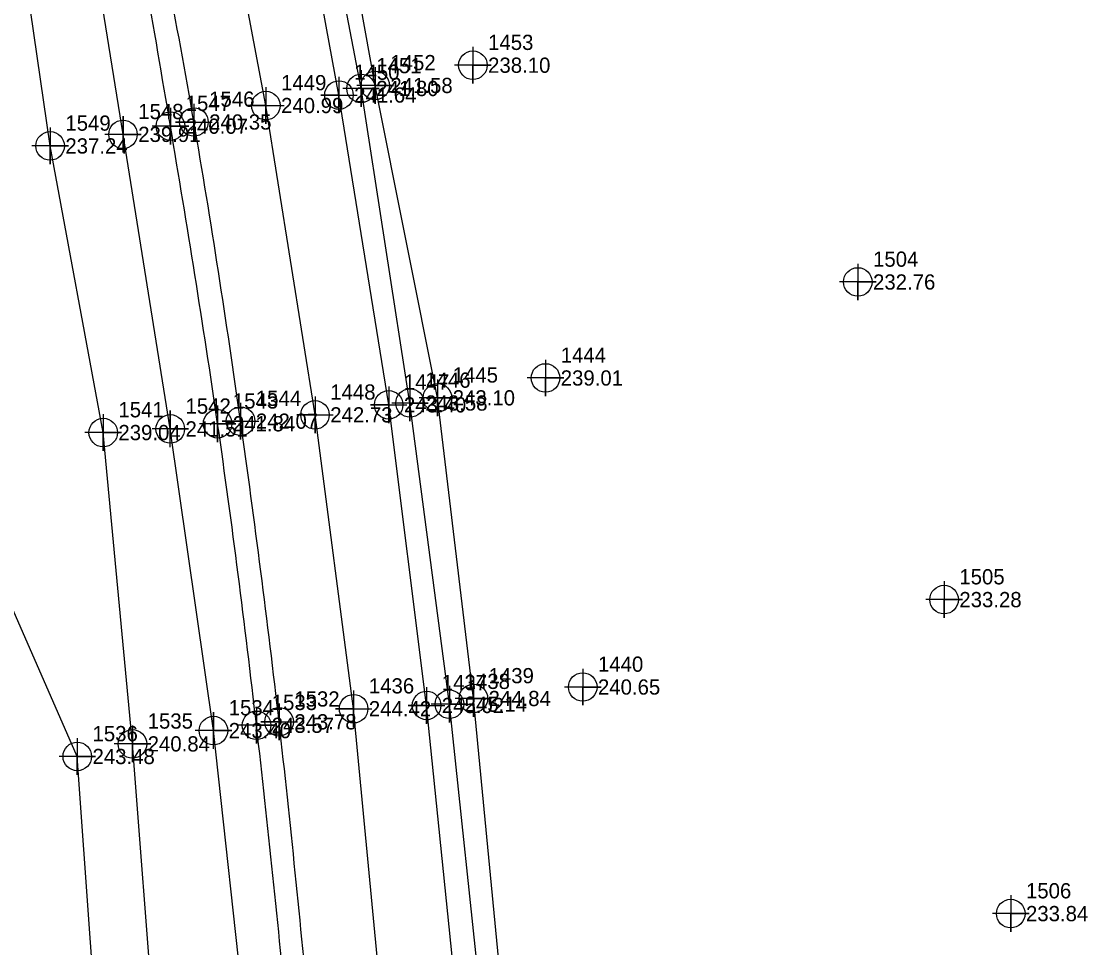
# Model space of a CAD drawing. Extents: x 2130962 to 2131465, y 643052 to 644206.
# Drawn here: x 2131170.6 to 2131345.6, y 643479.2 to 643631.2 of the extents above; entities that cross this region are included whole.
import ezdxf

# ---------------------------------------------------------------- set-up
doc = ezdxf.new("R2010")
doc.units = 0
for name, color, linetype in [('Exist DTM Breakline', 7, 'Continuous'), ('Exist DTM Breakline Cogo Elevation', 7, 'Continuous'), ('Exist DTM Breakline Cogo Number', 7, 'Continuous'), ('Exist DTM Breakline Cogo Point CELL', 7, 'Continuous'), ('Exist DTM Drainline', 7, 'Continuous'), ('Exist DTM Drainline Cogo Elevation', 7, 'Continuous'), ('Exist DTM Drainline Cogo Number', 7, 'Continuous'), ('Exist DTM Drainline Cogo Point CELL', 7, 'Continuous'), ('Exist DTM Regular Point CELL', 7, 'Continuous'), ('Exist DTM Regular Point Cogo Elevation', 7, 'Continuous'), ('Exist DTM Regular Point Cogo Number', 7, 'Continuous'), ('Exist Roads EOP', 7, 'Continuous'), ('Exist Roads EOP Cogo Elevation', 7, 'Continuous'), ('Exist Roads EOP Cogo Number', 7, 'Continuous'), ('Exist Roads EOP Cogo Point CELL', 7, 'Continuous'), ('Exist Roads EOT', 7, 'Continuous'), ('Exist Roads EOT Cogo Elevation', 7, 'Continuous'), ('Exist Roads EOT Cogo Number', 7, 'Continuous'), ('Exist Roads EOT Cogo Point CELL', 7, 'Continuous'), ('Exist Roads Soil', 7, 'Continuous'), ('Exist Roads Soil Cogo Elevation', 7, 'Continuous'), ('Exist Roads Soil Cogo Number', 7, 'Continuous'), ('Exist Roads Soil Cogo Point CELL', 7, 'Continuous')]:
    doc.layers.add(name, color=color, linetype=linetype)

msp = doc.modelspace()

# ---------------------------------------------------------------- linework, layer by layer
at = {"layer": 'Exist DTM Breakline'}
for points in [[(2131266.3306, 643269.372), (2131264.0776, 643319.4437), (2131258.8396, 643369.5498), (2131255.3671, 643419.5794), (2131249.6414, 643469.556), (2131244.7652, 643520.0623), (2131238.8778, 643569.4077), (2131228.6495, 643620.6699), (2131219.85, 643669.4823), (2131206.9682, 643717.8453), (2131195.8132, 643768.1497), (2131183.2404, 643816.8151), (2131169.0496, 643865.1461), (2131151.2314, 643913.4424), (2131130.7295, 643958.9736), (2131122.7411, 643983.0115)], [(2131000.7408, 643235.0731), (2131050.2503, 643235.0771), (2131099.3971, 643233.3967), (2131102.4734, 643233.467), (2131117.9784, 643240.6457), (2131141.4902, 643260.2289), (2131148.9668, 643267.309), (2131161.3925, 643274.3195), (2131169.1458, 643283.2692), (2131172.0772, 643292.493), (2131174.434, 643316.7319), (2131174.0607, 643347.0813), (2131174.2633, 643367.3367), (2131180.4607, 643413.966), (2131183.0424, 643464.7744), (2131179.7562, 643510.5479), (2131157.5016, 643561.2065), (2131139.0887, 643604.6918), (2131124.996, 643650.6897)]]:
    msp.add_lwpolyline(points, dxfattribs=at)
at = {"layer": 'Exist DTM Breakline Cogo Point CELL'}
for points in [[(2131228.6495, 643623.6699), (2131228.6495, 643617.6699), (2131228.6495, 643620.6699), (2131231.6495, 643620.6699), (2131225.6495, 643620.6699)], [(2131238.8778, 643572.4077), (2131238.8778, 643566.4077), (2131238.8778, 643569.4077), (2131241.8778, 643569.4077), (2131235.8778, 643569.4077)], [(2131244.7652, 643523.0623), (2131244.7652, 643517.0623), (2131244.7652, 643520.0623), (2131247.7652, 643520.0623), (2131241.7652, 643520.0623)], [(2131179.7562, 643513.5479), (2131179.7562, 643507.5479), (2131179.7562, 643510.5479), (2131182.7562, 643510.5479), (2131176.7562, 643510.5479)]]:
    msp.add_lwpolyline(points, dxfattribs=at)
for centre in [(2131228.6495, 643620.6699), (2131238.8778, 643569.4077), (2131244.7652, 643520.0623), (2131179.7562, 643510.5479)]:
    msp.add_circle(centre, 2.344, dxfattribs=at)
at = {"layer": 'Exist DTM Drainline'}
msp.add_lwpolyline([(2131000.2029, 643226.7228), (2131050.9884, 643228.9032), (2131099.0297, 643228.5605), (2131120.2968, 643239.3591), (2131144.9156, 643253.3469), (2131146.4739, 643252.3674), (2131154.3188, 643256.8046), (2131168.9618, 643265.5132), (2131176.6257, 643272.964), (2131179.8144, 643285.303), (2131183.3842, 643315.022), (2131190.1471, 643365.8731), (2131190.1489, 643413.686), (2131192.3886, 643466.4632), (2131188.8083, 643512.615), (2131184.0059, 643563.7066), (2131175.3, 643610.7482), (2131168.3784, 643658.7431), (2131156.7476, 643707.4708), (2131144.9036, 643754.0458), (2131132.9438, 643802.544), (2131118.0831, 643847.9475), (2131104.0084, 643896.8663), (2131096.3866, 643919.4077)], dxfattribs=at)
at = {"layer": 'Exist DTM Drainline Cogo Point CELL'}
for points in [[(2131175.3, 643613.7482), (2131175.3, 643607.7482), (2131175.3, 643610.7482), (2131178.3, 643610.7482), (2131172.3, 643610.7482)], [(2131184.0059, 643566.7066), (2131184.0059, 643560.7066), (2131184.0059, 643563.7066), (2131187.0059, 643563.7066), (2131181.0059, 643563.7066)], [(2131188.8083, 643515.615), (2131188.8083, 643509.615), (2131188.8083, 643512.615), (2131191.8083, 643512.615), (2131185.8083, 643512.615)]]:
    msp.add_lwpolyline(points, dxfattribs=at)
for centre in [(2131175.3, 643610.7482), (2131184.0059, 643563.7066), (2131188.8083, 643512.615)]:
    msp.add_circle(centre, 2.344, dxfattribs=at)
at = {"layer": 'Exist DTM Regular Point CELL'}
for points in [[(2131244.6876, 643626.9964), (2131244.6876, 643620.9964), (2131244.6876, 643623.9964), (2131247.6876, 643623.9964), (2131241.6876, 643623.9964)], [(2131307.874, 643591.4198), (2131307.874, 643585.4198), (2131307.874, 643588.4198), (2131310.874, 643588.4198), (2131304.874, 643588.4198)], [(2131256.6081, 643575.6655), (2131256.6081, 643569.6655), (2131256.6081, 643572.6655), (2131259.6081, 643572.6655), (2131253.6081, 643572.6655)], [(2131322.0371, 643539.2918), (2131322.0371, 643533.2918), (2131322.0371, 643536.2918), (2131325.0371, 643536.2918), (2131319.0371, 643536.2918)], [(2131262.7208, 643524.9497), (2131262.7208, 643518.9497), (2131262.7208, 643521.9497), (2131265.7208, 643521.9497), (2131259.7208, 643521.9497)], [(2131332.9747, 643487.761), (2131332.9747, 643481.761), (2131332.9747, 643484.761), (2131335.9747, 643484.761), (2131329.9747, 643484.761)]]:
    msp.add_lwpolyline(points, dxfattribs=at)
for centre in [(2131244.6876, 643623.9964), (2131307.874, 643588.4198), (2131256.6081, 643572.6655), (2131322.0371, 643536.2918), (2131262.7208, 643521.9497), (2131332.9747, 643484.761)]:
    msp.add_circle(centre, 2.344, dxfattribs=at)
at = {"layer": 'Exist Roads EOP'}
msp.add_lwpolyline([(2131264.2715, 643222.5647), (2131259.8757, 643269.3254), (2131257.0196, 643319.4043), (2131254.2561, 643369.6499), (2131250.0777, 643419.4187), (2131246.1511, 643469.0294), (2131240.8382, 643519.1271), (2131234.3674, 643568.5584), (2131226.3321, 643620.1808), (2131217.0271, 643668.7116), (2131205.6213, 643717.607), (2131192.0578, 643767.2595), (2131177.9714, 643815.0911), (2131162.2913, 643862.9344), (2131145.3604, 643910.8486), (2131126.9113, 643957.2915), (2131112.3691, 643996.1228)], dxfattribs=at)
msp.add_spline([(2131166.2495, 643216.6951), (2131171.8131, 643218.7244), (2131182.3713, 643223.9726), (2131191.8117, 643231.1489), (2131200.5013, 643239.6993), (2131208.8071, 643249.0697), (2131216.0672, 643259.0032), (2131218.7188, 643264.347), (2131220.5363, 643270.0958), (2131222.8445, 643282.0077), (2131224.3583, 643293.9245), (2131224.8763, 643317.7904), (2131222.0632, 643367.6716), (2131218.5448, 643416.8114), (2131214.3187, 643466.3462), (2131209.1735, 643515.6666), (2131202.7939, 643565.1545), (2131195.0475, 643613.9937), (2131186.4014, 643662.4763), (2131176.0113, 643711.405), (2131164.6154, 643759.8896), (2131151.874, 643807.8526), (2131137.8554, 643855.4065), (2131122.5733, 643902.8574), (2131105.9622, 643949.4862), (2131091.5349, 643988.0437)], degree=3, dxfattribs=at)
at = {"layer": 'Exist Roads EOP Cogo Point CELL'}
for points in [[(2131226.3321, 643623.1808), (2131226.3321, 643617.1808), (2131226.3321, 643620.1808), (2131229.3321, 643620.1808), (2131223.3321, 643620.1808)], [(2131195.0475, 643616.9937), (2131195.0475, 643610.9937), (2131195.0475, 643613.9937), (2131198.0475, 643613.9937), (2131192.0475, 643613.9937)], [(2131234.3674, 643571.5584), (2131234.3674, 643565.5584), (2131234.3674, 643568.5584), (2131237.3674, 643568.5584), (2131231.3674, 643568.5584)], [(2131202.7939, 643568.1545), (2131202.7939, 643562.1545), (2131202.7939, 643565.1545), (2131205.7939, 643565.1545), (2131199.7939, 643565.1545)], [(2131240.8382, 643522.1271), (2131240.8382, 643516.1271), (2131240.8382, 643519.1271), (2131243.8382, 643519.1271), (2131237.8382, 643519.1271)], [(2131209.1735, 643518.6666), (2131209.1735, 643512.6666), (2131209.1735, 643515.6666), (2131212.1735, 643515.6666), (2131206.1735, 643515.6666)]]:
    msp.add_lwpolyline(points, dxfattribs=at)
for centre in [(2131226.3321, 643620.1808), (2131195.0475, 643613.9937), (2131234.3674, 643568.5584), (2131202.7939, 643565.1545), (2131240.8382, 643519.1271), (2131209.1735, 643515.6666)]:
    msp.add_circle(centre, 2.344, dxfattribs=at)
at = {"layer": 'Exist Roads EOT'}
for points in [[(2131255.7894, 643269.2666), (2131252.7511, 643319.2443), (2131249.9083, 643369.5477), (2131246.3502, 643419.1778), (2131242.1933, 643468.6938), (2131237.0867, 643518.9193), (2131230.8671, 643568.2588), (2131222.7066, 643619.1047), (2131213.6442, 643668.3078), (2131202.755, 643717.0933), (2131189.234, 643766.4577), (2131174.9499, 643814.1787), (2131159.2111, 643861.933), (2131141.9103, 643909.6722), (2131123.7008, 643956.0828), (2131104.9436, 644003.1503), (2131086.2706, 644048.8072), (2131065.6997, 644094.9191), (2131044.3618, 644140.0645), (2131021.6804, 644185.4526)], [(2131237.6994, 643363.706), (2131234.1644, 643418.0043), (2131229.8934, 643468.0098), (2131225.1139, 643518.3873), (2131218.7748, 643566.6133), (2131210.7043, 643617.3811), (2131201.4139, 643666.7928), (2131191.4121, 643714.0755), (2131179.6696, 643764.3904), (2131167.3006, 643812.1237), (2131153.7359, 643860.4033), (2131138.3711, 643908.8544), (2131125.1607, 643951.4161)]]:
    msp.add_lwpolyline(points, dxfattribs=at)
msp.add_spline([(2131166.718, 643215.2083), (2131172.3866, 643217.1804), (2131211.4056, 643247.1499), (2131223.758, 643268.7314), (2131228.3848, 643317.935), (2131225.533, 643367.8628), (2131222.2486, 643417.1873), (2131217.9619, 643466.6275), (2131212.8794, 643516.2377), (2131206.5633, 643565.5764), (2131198.9021, 643614.6757), (2131189.6851, 643663.4055), (2131179.3985, 643712.1311), (2131168.3085, 643760.7185), (2131155.755, 643808.9129), (2131141.6748, 643856.5528), (2131126.5354, 643904.2758), (2131110.3559, 643951.0191), (2131092.4533, 643998.1348), (2131073.722, 644043.631), (2131053.1654, 644089.359), (2131032.0052, 644134.0908), (2131009.0644, 644179.3802)], degree=3, dxfattribs=at)
at = {"layer": 'Exist Roads EOT Cogo Point CELL'}
for points in [[(2131222.7066, 643622.1047), (2131222.7066, 643616.1047), (2131222.7066, 643619.1047), (2131219.7066, 643619.1047), (2131225.7066, 643619.1047)], [(2131210.7043, 643620.3811), (2131210.7043, 643614.3811), (2131210.7043, 643617.3811), (2131207.7043, 643617.3811), (2131213.7043, 643617.3811)], [(2131198.9021, 643617.6757), (2131198.9021, 643611.6757), (2131198.9021, 643614.6757), (2131195.9021, 643614.6757), (2131201.9021, 643614.6757)], [(2131230.8671, 643571.2588), (2131230.8671, 643565.2588), (2131230.8671, 643568.2588), (2131227.8671, 643568.2588), (2131233.8671, 643568.2588)], [(2131206.5633, 643568.5764), (2131206.5633, 643562.5764), (2131206.5633, 643565.5764), (2131203.5633, 643565.5764), (2131209.5633, 643565.5764)], [(2131218.7748, 643569.6133), (2131218.7748, 643563.6133), (2131218.7748, 643566.6133), (2131215.7748, 643566.6133), (2131221.7748, 643566.6133)], [(2131225.1139, 643521.3873), (2131225.1139, 643515.3873), (2131225.1139, 643518.3873), (2131222.1139, 643518.3873), (2131228.1139, 643518.3873)], [(2131237.0867, 643521.9193), (2131237.0867, 643515.9193), (2131237.0867, 643518.9193), (2131234.0867, 643518.9193), (2131240.0867, 643518.9193)], [(2131212.8794, 643519.2377), (2131212.8794, 643513.2377), (2131212.8794, 643516.2377), (2131209.8794, 643516.2377), (2131215.8794, 643516.2377)]]:
    msp.add_lwpolyline(points, dxfattribs=at)
for centre in [(2131222.7066, 643619.1047), (2131210.7043, 643617.3811), (2131198.9021, 643614.6757), (2131230.8671, 643568.2588), (2131218.7748, 643566.6133), (2131206.5633, 643565.5764), (2131225.1139, 643518.3873), (2131237.0867, 643518.9193), (2131212.8794, 643516.2377)]:
    msp.add_circle(centre, 2.344, dxfattribs=at)
at = {"layer": 'Exist Roads Soil'}
msp.add_lwpolyline([(2131224.8674, 643317.753), (2131220.141, 643317.6487), (2131216.7544, 643367.544), (2131211.084, 643416.163), (2131207.4344, 643466.363), (2131202.1097, 643514.7948), (2131195.0195, 643564.3052), (2131187.2605, 643612.6498), (2131179.506, 643660.9545), (2131164.8317, 643709.0781), (2131153.9175, 643755.9834), (2131140.8896, 643804.492), (2131127.2512, 643851.9231), (2131113.4771, 643899.8082), (2131083.6685, 643994.997), (2131066.191, 644040.9476), (2131049.1539, 644087.3869)], dxfattribs=at)
at = {"layer": 'Exist Roads Soil Cogo Point CELL'}
for points in [[(2131187.2605, 643609.6498), (2131187.2605, 643615.6498), (2131187.2605, 643612.6498), (2131190.2605, 643612.6498), (2131184.2605, 643612.6498)], [(2131195.0195, 643561.3052), (2131195.0195, 643567.3052), (2131195.0195, 643564.3052), (2131198.0195, 643564.3052), (2131192.0195, 643564.3052)], [(2131202.1097, 643511.7948), (2131202.1097, 643517.7948), (2131202.1097, 643514.7948), (2131205.1097, 643514.7948), (2131199.1097, 643514.7948)]]:
    msp.add_lwpolyline(points, dxfattribs=at)
for centre in [(2131187.2605, 643612.6498), (2131195.0195, 643564.3052), (2131202.1097, 643514.7948)]:
    msp.add_circle(centre, 2.344, dxfattribs=at)

# ---------------------------------------------------------------- texts
at = {"layer": 'Exist DTM Breakline Cogo Elevation'}
for s, p in [('241.58', (2131231.1495, 643619.4199)), ('243.10', (2131241.3778, 643568.1577)), ('244.84', (2131247.2652, 643518.8123)), ('243.48', (2131182.2562, 643509.2979))]:
    msp.add_text(s, height=2.5, dxfattribs=at).set_placement(p)
at = {"layer": 'Exist DTM Breakline Cogo Number'}
for s, p in [('1452', (2131231.1495, 643623.1699)), ('1445', (2131241.3778, 643571.9077)), ('1439', (2131247.2652, 643522.5623)), ('1536', (2131182.2562, 643513.0479))]:
    msp.add_text(s, height=2.5, dxfattribs=at).set_placement(p)
at = {"layer": 'Exist DTM Drainline Cogo Elevation'}
for s, p in [('237.24', (2131177.8, 643609.4982)), ('239.04', (2131186.5059, 643562.4566)), ('240.84', (2131191.3083, 643511.365))]:
    msp.add_text(s, height=2.5, dxfattribs=at).set_placement(p)
at = {"layer": 'Exist DTM Drainline Cogo Number'}
for s, p in [('1549', (2131177.8, 643613.2482)), ('1541', (2131186.5059, 643566.2066)), ('1535', (2131191.3083, 643515.115))]:
    msp.add_text(s, height=2.5, dxfattribs=at).set_placement(p)
at = {"layer": 'Exist DTM Regular Point Cogo Elevation'}
for s, p in [('238.10', (2131247.1876, 643622.7464)), ('232.76', (2131310.374, 643587.1698)), ('239.01', (2131259.1081, 643571.4155)), ('233.28', (2131324.5371, 643535.0418)), ('240.65', (2131265.2208, 643520.6997)), ('233.84', (2131335.4747, 643483.511))]:
    msp.add_text(s, height=2.5, dxfattribs=at).set_placement(p)
at = {"layer": 'Exist DTM Regular Point Cogo Number'}
for s, p in [('1453', (2131247.1876, 643626.4964)), ('1504', (2131310.374, 643590.9198)), ('1444', (2131259.1081, 643575.1655)), ('1505', (2131324.5371, 643538.7918)), ('1440', (2131265.2208, 643524.4497)), ('1506', (2131335.4747, 643487.261))]:
    msp.add_text(s, height=2.5, dxfattribs=at).set_placement(p)
at = {"layer": 'Exist Roads EOP Cogo Elevation'}
for s, p in [('241.80', (2131228.8321, 643618.9308)), ('240.07', (2131197.5475, 643612.7437)), ('243.58', (2131236.8674, 643567.3084)), ('241.84', (2131205.2939, 643563.9045)), ('245.14', (2131243.3382, 643517.8771)), ('243.57', (2131211.6735, 643514.4166))]:
    msp.add_text(s, height=2.5, dxfattribs=at).set_placement(p)
at = {"layer": 'Exist Roads EOP Cogo Number'}
for s, p in [('1451', (2131228.8321, 643622.6808)), ('1547', (2131197.5475, 643616.4937)), ('1446', (2131236.8674, 643571.0584)), ('1543', (2131205.2939, 643567.6545)), ('1438', (2131243.3382, 643521.6271)), ('1533', (2131211.6735, 643518.1666))]:
    msp.add_text(s, height=2.5, dxfattribs=at).set_placement(p)
at = {"layer": 'Exist Roads EOT Cogo Elevation'}
for s, p in [('241.64', (2131225.2066, 643617.8547)), ('240.99', (2131213.2043, 643616.1311)), ('240.35', (2131201.4021, 643613.4257)), ('243.40', (2131233.3671, 643567.0088)), ('242.07', (2131209.0633, 643564.3264)), ('242.73', (2131221.2748, 643565.3633)), ('244.42', (2131227.6139, 643517.1373)), ('245.02', (2131239.5867, 643517.6693)), ('243.78', (2131215.3794, 643514.9877))]:
    msp.add_text(s, height=2.5, dxfattribs=at).set_placement(p)
at = {"layer": 'Exist Roads EOT Cogo Number'}
for s, p in [('1450', (2131225.2066, 643621.6047)), ('1449', (2131213.2043, 643619.8811)), ('1546', (2131201.4021, 643617.1757)), ('1447', (2131233.3671, 643570.7588)), ('1544', (2131209.0633, 643568.0764)), ('1448', (2131221.2748, 643569.1133)), ('1436', (2131227.6139, 643520.8873)), ('1437', (2131239.5867, 643521.4193)), ('1532', (2131215.3794, 643518.7377))]:
    msp.add_text(s, height=2.5, dxfattribs=at).set_placement(p)
at = {"layer": 'Exist Roads Soil Cogo Elevation'}
for s, p in [('239.91', (2131189.7605, 643611.3998)), ('241.51', (2131197.5195, 643563.0552)), ('243.40', (2131204.6097, 643513.5448))]:
    msp.add_text(s, height=2.5, dxfattribs=at).set_placement(p)
at = {"layer": 'Exist Roads Soil Cogo Number'}
for s, p in [('1548', (2131189.7605, 643615.1498)), ('1542', (2131197.5195, 643566.8052)), ('1534', (2131204.6097, 643517.2948))]:
    msp.add_text(s, height=2.5, dxfattribs=at).set_placement(p)

doc.saveas('drawing.dxf')
